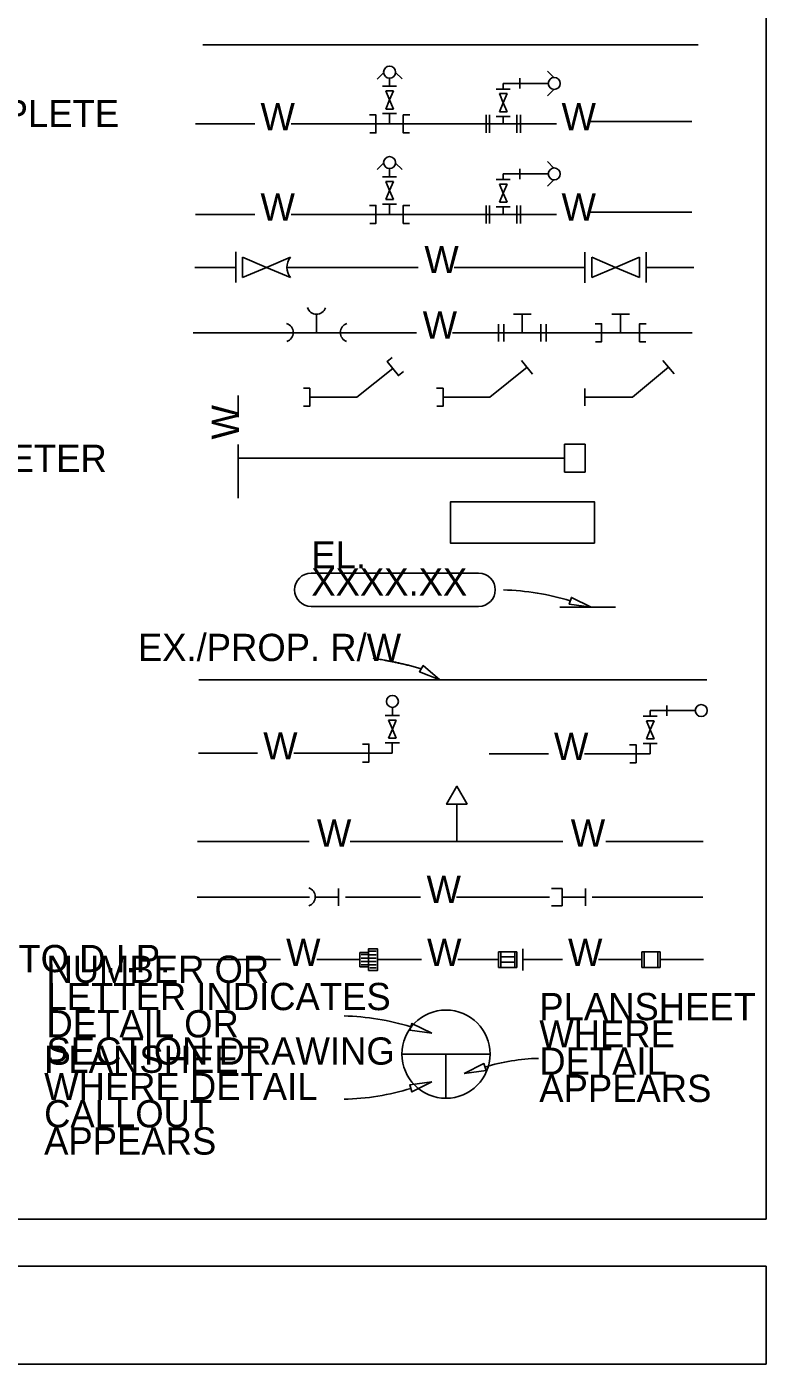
# Model space of a CAD drawing. Extents: x 837 to 1117, y 1316 to 1424.
# Drawn here: x 859.18 to 862.44, y 1410.46 to 1416.35 of the extents above; entities that cross this region are included whole.
import ezdxf

# ---------------------------------------------------------------- set-up
doc = ezdxf.new("R2010")
doc.units = 0
for name, color, linetype in [('BASEMAP', 7, 'Continuous'), ('DIMS', 7, 'Continuous'), ('LLINES', 7, 'Continuous'), ('Right-Of-Way', 7, 'Continuous'), ('TEXT', 7, 'Continuous')]:
    doc.layers.add(name, color=color, linetype=linetype)

msp = doc.modelspace()

# ---------------------------------------------------------------- linework, layer by layer
at = {"layer": 'BASEMAP'}
for p, q in [((862.4361, 1411.0955), (862.4361, 1420.0653)), ((855.1875, 1411.0955), (862.4361, 1411.0955)), ((855.1874, 1410.8886), (862.4354, 1410.8886)), ((862.4354, 1410.4566), (862.4354, 1410.8886)), ((855.1874, 1410.4566), (862.4354, 1410.4566))]:
    msp.add_line(p, q, dxfattribs=at)
at = {"layer": 'DIMS'}
msp.add_line((860.1304, 1415.2411), (860.1304, 1415.3304), dxfattribs=at)
at = {"layer": 'LLINES'}
for p, q in [((859.9546, 1416.2656), (862.1357, 1416.2656)), ((860.7513, 1416.1424), (860.7232, 1416.1142)), ((860.7774, 1416.0829), (860.7774, 1416.1193)), ((860.804, 1416.1436), (860.8322, 1416.1154)), ((861.3506, 1416.1182), (861.3506, 1416.0726)), ((861.5008, 1416.1216), (861.4729, 1416.1495)), ((860.7459, 1416.0829), (860.8081, 1416.0829)), ((860.7604, 1416.0629), (860.7774, 1416.0228)), ((860.7604, 1416.0629), (860.7944, 1416.0629)), ((860.7944, 1416.0629), (860.7774, 1416.0228)), ((861.2464, 1416.0707), (861.3086, 1416.0707)), ((861.2779, 1416.0707), (861.2779, 1416.0954)), ((861.501, 1416.0692), (861.4731, 1416.0413)), ((860.7774, 1416.0228), (860.7604, 1415.9828)), ((860.7944, 1415.9828), (860.7774, 1416.0228)), ((861.2609, 1416.0507), (861.2949, 1416.0507)), ((861.2609, 1416.0507), (861.2779, 1416.0106)), ((861.2779, 1416.0106), (861.2609, 1415.9706)), ((861.2949, 1416.0507), (861.2779, 1416.0106)), ((861.2949, 1415.9706), (861.2779, 1416.0106)), ((860.7459, 1415.9628), (860.8081, 1415.9628)), ((860.7604, 1415.9828), (860.7944, 1415.9828)), ((860.7774, 1415.9628), (860.7774, 1415.9173)), ((861.2024, 1415.8777), (861.2024, 1415.9568)), ((861.2178, 1415.8777), (861.2178, 1415.9568)), ((861.2464, 1415.9506), (861.3086, 1415.9506)), ((861.2609, 1415.9706), (861.2949, 1415.9706)), ((861.2779, 1415.9506), (861.2779, 1415.9173)), ((861.338, 1415.8777), (861.338, 1415.9568)), ((861.3535, 1415.8777), (861.3535, 1415.9568)), ((859.9234, 1415.9173), (860.1842, 1415.9173)), ((860.3439, 1415.9173), (861.5117, 1415.9173)), ((861.6633, 1415.9272), (862.1082, 1415.9272)), ((860.7513, 1415.744), (860.7232, 1415.7159)), ((860.7774, 1415.6845), (860.7774, 1415.7209)), ((860.804, 1415.7452), (860.8322, 1415.7171)), ((861.3506, 1415.7198), (861.3506, 1415.6743)), ((861.5008, 1415.7232), (861.4729, 1415.7511)), ((860.7459, 1415.6845), (860.8081, 1415.6845)), ((860.7604, 1415.6645), (860.7774, 1415.6245)), ((860.7604, 1415.6645), (860.7944, 1415.6645)), ((860.7944, 1415.6645), (860.7774, 1415.6245)), ((861.2464, 1415.6723), (861.3086, 1415.6723)), ((861.2609, 1415.6523), (861.2949, 1415.6523)), ((861.2609, 1415.6523), (861.2779, 1415.6123)), ((861.2779, 1415.6723), (861.2779, 1415.6971)), ((861.2949, 1415.6523), (861.2779, 1415.6123)), ((861.501, 1415.6709), (861.4731, 1415.643)), ((860.7774, 1415.6245), (860.7604, 1415.5845)), ((860.7604, 1415.5845), (860.7944, 1415.5845)), ((860.7944, 1415.5845), (860.7774, 1415.6245)), ((861.2779, 1415.6123), (861.2609, 1415.5723)), ((861.2949, 1415.5723), (861.2779, 1415.6123)), ((860.7459, 1415.5645), (860.8081, 1415.5645)), ((860.7774, 1415.5645), (860.7774, 1415.5189)), ((861.2024, 1415.4794), (861.2024, 1415.5585)), ((861.2178, 1415.4794), (861.2178, 1415.5585)), ((861.2464, 1415.5523), (861.3086, 1415.5523)), ((861.2609, 1415.5723), (861.2949, 1415.5723)), ((861.2779, 1415.5523), (861.2779, 1415.5189)), ((861.338, 1415.4794), (861.338, 1415.5585)), ((861.3535, 1415.4794), (861.3535, 1415.5585)), ((861.6633, 1415.5289), (862.1082, 1415.5289)), ((859.9234, 1415.5189), (860.1842, 1415.5189)), ((860.3439, 1415.5189), (861.5117, 1415.5189)), ((860.1004, 1415.2193), (860.1004, 1415.3541)), ((861.6373, 1415.2181), (861.6373, 1415.3529)), ((861.9075, 1415.2184), (861.9075, 1415.3532)), ((860.1304, 1415.3304), (860.2355, 1415.2858)), ((860.3407, 1415.3304), (860.2355, 1415.2858)), ((861.6674, 1415.2411), (861.6674, 1415.3304)), ((861.6674, 1415.3304), (861.7725, 1415.2858)), ((861.8776, 1415.3304), (861.7725, 1415.2858)), ((861.8776, 1415.2411), (861.8776, 1415.3304)), ((859.9201, 1415.2858), (860.1004, 1415.2858)), ((860.2355, 1415.2858), (860.1304, 1415.2411)), ((860.3407, 1415.2411), (860.2355, 1415.2858)), ((860.3248, 1415.2858), (860.9029, 1415.2858)), ((861.6373, 1415.2858), (861.0623, 1415.2858)), ((861.6674, 1415.2411), (861.7725, 1415.2858)), ((861.7725, 1415.2858), (861.8776, 1415.2411)), ((862.1178, 1415.2858), (861.9075, 1415.2858)), ((860.4559, 1415.0796), (860.4559, 1414.9978)), ((861.3234, 1415.0796), (861.4002, 1415.0796)), ((861.3618, 1415.0796), (861.3618, 1414.9978)), ((861.7565, 1415.0796), (861.8333, 1415.0796)), ((861.7949, 1415.0796), (861.7949, 1414.9978)), ((859.9127, 1414.9978), (860.8954, 1414.9978)), ((861.6171, 1414.9978), (861.0549, 1414.9978)), ((861.2565, 1414.9594), (861.2565, 1415.0362)), ((861.28, 1414.9594), (861.28, 1415.0362)), ((861.4436, 1415.0362), (861.4436, 1414.9594)), ((861.4671, 1415.0362), (861.4671, 1414.9594)), ((861.6171, 1414.9978), (861.6918, 1414.9978)), ((861.6898, 1414.9978), (861.9, 1414.9978)), ((862.1103, 1414.9978), (861.9, 1414.9978)), ((860.6326, 1414.7138), (860.7918, 1414.8405)), ((861.2195, 1414.7138), (861.3829, 1414.8461)), ((861.407, 1414.8162), (861.3587, 1414.8759)), ((861.8469, 1414.7138), (862.0059, 1414.8469)), ((862.0305, 1414.8175), (861.9812, 1414.8764)), ((860.1099, 1414.7212), (860.1099, 1414.6257)), ((860.4262, 1414.7138), (860.6326, 1414.7138)), ((861.0131, 1414.7138), (861.2195, 1414.7138)), ((861.6366, 1414.6754), (861.6366, 1414.7522)), ((861.6366, 1414.7138), (861.8469, 1414.7138)), ((860.1099, 1414.5066), (860.1099, 1414.2695)), ((861.5473, 1414.5071), (861.638, 1414.5071)), ((861.5473, 1414.384), (861.5473, 1414.5071)), ((861.638, 1414.5071), (861.638, 1414.384)), ((860.1099, 1414.4455), (861.5473, 1414.4455)), ((861.638, 1414.384), (861.5473, 1414.384)), ((861.6649, 1413.7894), (861.5276, 1413.7894)), ((861.6649, 1413.7894), (861.7724, 1413.7894)), ((860.7896, 1413.3128), (860.7896, 1413.3492)), ((861.9978, 1413.3575), (861.9978, 1413.312)), ((860.7581, 1413.3128), (860.8204, 1413.3128)), ((860.7726, 1413.2928), (860.8066, 1413.2928)), ((860.7726, 1413.2928), (860.7896, 1413.2528)), ((860.8066, 1413.2928), (860.7896, 1413.2528)), ((861.8937, 1413.31), (861.9559, 1413.31)), ((861.9082, 1413.29), (861.9252, 1413.25)), ((861.9082, 1413.29), (861.9421, 1413.29)), ((861.9252, 1413.31), (861.9252, 1413.3347)), ((861.9421, 1413.29), (861.9252, 1413.25)), ((860.7896, 1413.2528), (860.7726, 1413.2128)), ((860.8066, 1413.2128), (860.7896, 1413.2528)), ((861.9252, 1413.25), (861.9082, 1413.21)), ((861.9421, 1413.21), (861.9252, 1413.25)), ((860.7581, 1413.1928), (860.8204, 1413.1928)), ((860.7726, 1413.2128), (860.8066, 1413.2128)), ((860.7893, 1413.1928), (860.7893, 1413.1472)), ((861.8937, 1413.19), (861.9559, 1413.19)), ((861.9082, 1413.21), (861.9421, 1413.21)), ((861.9248, 1413.19), (861.9248, 1413.1444)), ((859.9353, 1413.1472), (860.1961, 1413.1472)), ((860.3558, 1413.1472), (860.7893, 1413.1472)), ((861.2157, 1413.1444), (861.4765, 1413.1444)), ((861.6362, 1413.1444), (861.9248, 1413.1444)), ((859.9317, 1412.7587), (860.4229, 1412.7587)), ((860.6039, 1412.7587), (861.5408, 1412.7587)), ((861.7303, 1412.7587), (862.1579, 1412.7587)), ((860.5529, 1412.4746), (860.5529, 1412.5514)), ((861.5373, 1412.4746), (861.5373, 1412.5514)), ((861.6404, 1412.4746), (861.6404, 1412.5514)), ((859.9303, 1412.513), (860.4245, 1412.513)), ((860.5829, 1412.513), (860.9131, 1412.513)), ((861.482, 1412.513), (861.0725, 1412.513)), ((862.1565, 1412.513), (861.6701, 1412.513)), ((861.364, 1412.19), (861.364, 1412.286)), ((859.9292, 1412.238), (860.2969, 1412.238)), ((860.4566, 1412.238), (860.6468, 1412.238)), ((860.7236, 1412.238), (860.9176, 1412.238)), ((861.0773, 1412.238), (861.2577, 1412.238)), ((861.2577, 1412.2033), (861.2577, 1412.2727)), ((861.2577, 1412.2727), (861.3382, 1412.2727)), ((861.2673, 1412.2033), (861.2673, 1412.2727)), ((861.2673, 1412.2497), (861.3286, 1412.2497)), ((861.3286, 1412.2727), (861.3286, 1412.2033)), ((861.3382, 1412.2727), (861.3382, 1412.2033)), ((861.364, 1412.238), (861.5384, 1412.238)), ((861.6981, 1412.238), (861.8883, 1412.238)), ((861.8883, 1412.2727), (861.9689, 1412.2727)), ((861.8883, 1412.2033), (861.8883, 1412.2727)), ((861.8979, 1412.2033), (861.8979, 1412.2727)), ((861.9593, 1412.2727), (861.9593, 1412.2033)), ((861.9689, 1412.2727), (861.9689, 1412.2033)), ((861.9689, 1412.238), (862.1591, 1412.238)), ((861.3382, 1412.2033), (861.2577, 1412.2033)), ((861.2673, 1412.2267), (861.3286, 1412.2267)), ((861.9689, 1412.2033), (861.8883, 1412.2033)), ((860.8316, 1411.8219), (861.22, 1411.8219)), ((861.0258, 1411.8219), (861.0258, 1411.6277))]:
    msp.add_line(p, q, dxfattribs=at)
for points in [[(860.6888, 1415.9568), (860.7173, 1415.9568), (860.7173, 1415.8777), (860.6899, 1415.8777)], [(860.866, 1415.9568), (860.8375, 1415.9568), (860.8375, 1415.8777), (860.8649, 1415.8777)], [(860.6888, 1415.5585), (860.7173, 1415.5585), (860.7173, 1415.4794), (860.6899, 1415.4794)], [(860.866, 1415.5585), (860.8375, 1415.5585), (860.8375, 1415.4794), (860.8649, 1415.4794)], [(861.6828, 1415.0374), (861.7113, 1415.0374), (861.7113, 1414.9583), (861.6839, 1414.9583)], [(861.907, 1415.0374), (861.8785, 1415.0374), (861.8785, 1414.9583), (861.9059, 1414.9583)], [(860.8387, 1414.8273), (860.8164, 1414.8096), (860.7672, 1414.8715), (860.7886, 1414.8885)], [(860.3977, 1414.7533), (860.4262, 1414.7533), (860.4262, 1414.6742), (860.3988, 1414.6742)], [(860.9846, 1414.7533), (861.0131, 1414.7533), (861.0131, 1414.6742), (860.9857, 1414.6742)], [(861.1696, 1413.9395), (860.4322, 1413.9395)], [(860.4322, 1413.7927), (861.1696, 1413.7927)], [(860.6576, 1413.1868), (860.6861, 1413.1868), (860.6861, 1413.1077), (860.6588, 1413.1077)], [(861.8346, 1413.184), (861.8631, 1413.184), (861.8631, 1413.1049), (861.8357, 1413.1049)]]:
    msp.add_lwpolyline(points, dxfattribs=at)
msp.add_lwpolyline([(861.1197, 1412.9224), (861.0741, 1413.0013), (861.0285, 1412.9224)], close=True, dxfattribs=at)
for centre, radius in [((860.7776, 1416.1452), 0.0264), ((861.5026, 1416.0954), 0.0262), ((860.7776, 1415.7468), 0.0264), ((861.5026, 1415.6971), 0.0262), ((860.7899, 1413.3751), 0.0264), ((862.1498, 1413.3347), 0.0262), ((861.0258, 1411.8219), 0.1942)]:
    msp.add_circle(centre, radius, dxfattribs=at)
for centre, radius, start, end in [((860.4559, 1415.1214), 0.0418, 198.09654, 340.27157), ((860.3111, 1414.9987), 0.0418, 289.72843, 71.90346), ((860.6023, 1414.9987), 0.0418, 108.09654, 250.27157), ((860.4322, 1413.8661), 0.0734, 90, 270), ((861.1696, 1413.8661), 0.0734, 270, 90), ((860.4081, 1412.5139), 0.0418, 289.72843, 71.90346)]:
    msp.add_arc(centre, radius, start, end, dxfattribs=at)
at = {"layer": 'Right-Of-Way'}
msp.add_line((859.9376, 1413.4692), (862.1738, 1413.4692), dxfattribs=at)
at = {"layer": 'TEXT'}
for p, q in [((861.4764, 1416.0954), (861.2779, 1416.0954)), ((861.4764, 1415.6971), (861.2779, 1415.6971)), ((862.1236, 1413.3347), (861.9252, 1413.3347)), ((861.0742, 1412.9224), (861.0742, 1412.7587)), ((861.5373, 1412.5514), (861.49, 1412.5514)), ((860.5529, 1412.513), (860.4499, 1412.513)), ((861.5373, 1412.4746), (861.49, 1412.4746)), ((861.6404, 1412.513), (861.5373, 1412.513)), ((860.6516, 1412.26), (860.6804, 1412.26)), ((860.6516, 1412.245), (860.6804, 1412.245)), ((860.6516, 1412.23), (860.6804, 1412.23)), ((860.6895, 1412.2747), (860.7183, 1412.2747)), ((860.6895, 1412.2597), (860.7183, 1412.2597)), ((860.6895, 1412.2447), (860.7183, 1412.2447)), ((860.6895, 1412.2297), (860.7183, 1412.2297)), ((860.6516, 1412.215), (860.6804, 1412.215)), ((860.6895, 1412.2147), (860.7183, 1412.2147)), ((860.6899, 1412.2012), (860.7187, 1412.2012))]:
    msp.add_line(p, q, dxfattribs=at)
for points in [[(861.6791, 1414.071), (861.6791, 1414.2542), (861.0459, 1414.2542), (861.0459, 1414.071)], [(861.6649, 1413.7894), (861.5684, 1413.8024), (861.5778, 1413.8329)], [(860.9994, 1413.4692), (860.9091, 1413.5054), (860.9257, 1413.5327)], [(860.6852, 1412.19), (860.6852, 1412.286), (860.7236, 1412.286), (860.7236, 1412.19)], [(860.6468, 1412.2068), (860.6468, 1412.2692), (860.6852, 1412.2692), (860.6852, 1412.2068)], [(860.963, 1411.9138), (860.8665, 1411.9268), (860.8759, 1411.9574)], [(861.1056, 1411.7368), (861.2021, 1411.7498), (861.1927, 1411.7804)], [(860.963, 1411.6994), (860.8665, 1411.6864), (860.8759, 1411.6558)]]:
    msp.add_lwpolyline(points, close=True, dxfattribs=at)
for centre, radius, start, end in [((860.3954, 1415.2858), 0.0706, 140.79339, 219.20661), ((861.2534, 1412.7801), 1.0856, 72.87354, 88.66672), ((861.2534, 1412.7801), 1.0856, 72.87354, 88.66672), ((860.5515, 1410.9046), 1.0856, 72.87354, 88.66672), ((860.5515, 1410.9046), 1.0856, 72.87354, 88.66672), ((861.4532, 1410.9351), 0.8685, 91.33328, 107.12646), ((861.4532, 1410.9351), 0.8685, 91.33328, 107.12646), ((860.5515, 1412.7086), 1.0856, 271.33328, 287.12646), ((860.5515, 1412.7086), 1.0856, 271.33328, 287.12646)]:
    msp.add_arc(centre, radius, start, end, dxfattribs=at)
msp.add_open_spline([(860.9172, 1413.5182), (860.7507, 1413.5695), (860.5766, 1413.5736), (860.7506, 1413.5696), (860.9169, 1413.5184)], degree=4, dxfattribs=at)

# ---------------------------------------------------------------- texts
at = {"layer": 'LLINES'}
for s, p in [('PROPOSED FIRE HYDRANT 6" x 4" x 2 1/2" COMPLETE', (855.4295, 1415.9033)), ('W ', (860.209, 1415.8894)), ('W ', (861.5347, 1415.8894)), ('W ', (860.209, 1415.4911)), ('W ', (861.5347, 1415.4911)), ('W ', (860.9305, 1415.2604)), ('W ', (860.9231, 1414.9725)), ('DOMESTIC SERVICE CONNECTION & WATER METER', (855.431, 1414.3852)), ('EL. ', (860.4327, 1413.9603)), ('XXXX.XX', (860.4327, 1413.8403)), ('EX./PROP. R/W', (859.669, 1413.5525)), ('W ', (860.2209, 1413.1194)), ('W ', (861.5013, 1413.1166)), ('W ', (860.4574, 1412.7351)), ('W ', (861.5753, 1412.7351)), ('W ', (860.9402, 1412.4877)), ('D.I.P. TO D.I.P.', (858.697, 1412.1828)), ('W ', (860.3217, 1412.2101)), ('W ', (860.9424, 1412.2101)), ('W ', (861.5632, 1412.2101)), ('NUMBER OR ', (859.2666, 1412.1356)), ('LETTER INDICATES ', (859.2666, 1412.0156)), ('PLANSHEET ', (861.4366, 1411.9713)), ('DETAIL OR ', (859.2666, 1411.8956)), ('WHERE ', (861.4366, 1411.8513)), ('SECTION DRAWING', (859.2666, 1411.7756)), ('PLANSHEET ', (859.2562, 1411.7396)), ('DETAIL ', (861.4366, 1411.7313)), ('WHERE DETAIL ', (859.2562, 1411.6196)), ('APPEARS', (861.4366, 1411.6113)), ('CALLOUT ', (859.2562, 1411.4996)), ('APPEARS', (859.2562, 1411.3796))]:
    msp.add_text(s, height=0.12, dxfattribs=at).set_placement(p)
msp.add_text('W ', height=0.12, rotation=90, dxfattribs=at).set_placement((860.1143, 1414.5281))

doc.saveas('drawing.dxf')
